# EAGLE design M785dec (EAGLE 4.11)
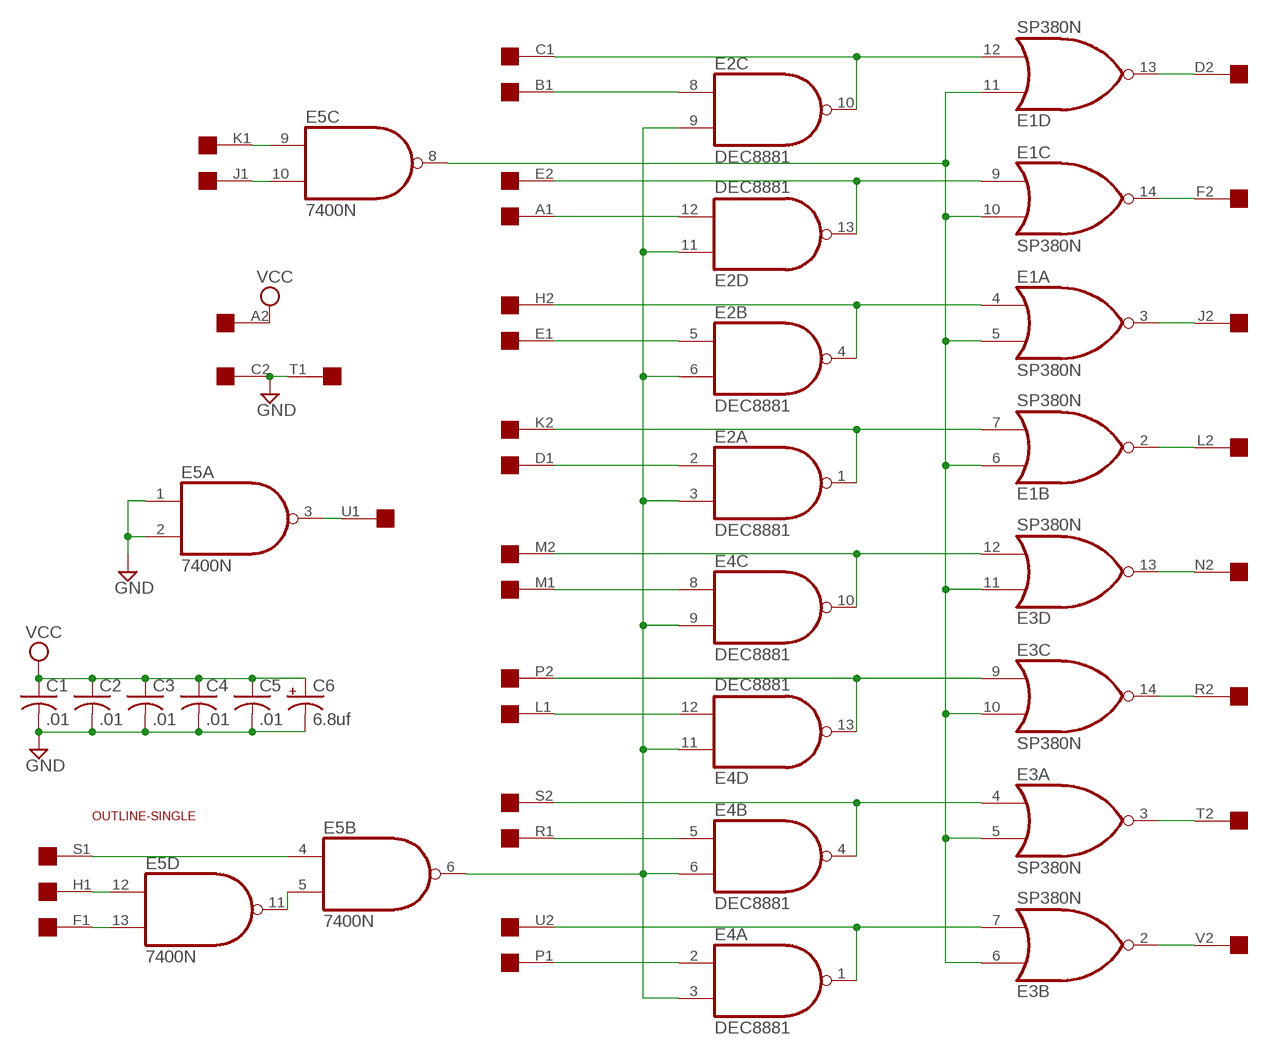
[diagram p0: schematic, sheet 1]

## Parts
C1  .01  C-US050-025X075  [C050-025X075]
C2  .01  C-US050-025X075  [C050-025X075]
C3  .01  C-US050-025X075  [C050-025X075]
C4  .01  C-US050-025X075  [C050-025X075]
C5  .01  C-US050-025X075  [C050-025X075]
C6  6.8uf  CPOL-USE15-5AXIAL  [E15-5]
E1  SP380N  [DIL14]
E2  DEC8881  7401N  [DIL14]
E3  SP380N  [DIL14]
E4  DEC8881  7401N  [DIL14]
E5  7400N  [DIL14]
U$1  SINGLE  [EDGE-CON2]
U$2  OUTLINE-SINGLE  [SINGLE]

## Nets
GND: C1.2 C2.2 C3.2 C4.2 C5.2 C6.- E5.1(A:I0) E5.2(A:I1) U$1.C2 U$1.T1
N$1: E1.5(A:I1) E1.6(B:I0) E1.10(C:I1) E1.11(D:I0) E3.5(A:I1) E3.6(B:I0) E3.10(C:I1) E3.11(D:I0) E5.8(C:O)
N$2: E2.3(A:I1) E2.6(B:I1) E2.9(C:I1) E2.11(D:I0) E4.3(A:I1) E4.6(B:I1) E4.9(C:I1) E4.11(D:I0) E5.6(B:O)
N$3: E3.12(D:I1) E4.10(C:O) U$1.M2
N$4: E3.7(B:I1) E4.1(A:O) U$1.U2
N$5: E4.2(A:I0) U$1.P1
N$6: E4.5(B:I0) U$1.R1
N$7: E3.4(A:I0) E4.4(B:O) U$1.S2
N$8: E4.12(D:I1) U$1.L1
N$9: E3.9(C:I0) E4.13(D:O) U$1.P2
N$10: E4.8(C:I0) U$1.M1
N$11: E1.12(D:I1) E2.10(C:O) U$1.C1
N$12: E2.8(C:I0) U$1.B1
N$13: E1.9(C:I0) E2.13(D:O) U$1.E2
N$14: E2.12(D:I1) U$1.A1
N$15: E1.4(A:I0) E2.4(B:O) U$1.H2
N$16: E2.5(B:I0) U$1.E1
N$17: E1.7(B:I1) E2.1(A:O) U$1.K2
N$18: E2.2(A:I0) U$1.D1
N$19: E5.9(C:I0) U$1.K1
N$20: E5.10(C:I1) U$1.J1
N$21: E1.13(D:O) U$1.D2
N$22: E1.14(C:O) U$1.F2
N$23: E1.3(A:O) U$1.J2
N$24: E1.2(B:O) U$1.L2
N$25: E3.13(D:O) U$1.N2
N$26: E3.14(C:O) U$1.R2
N$27: E3.3(A:O) U$1.T2
N$28: E3.2(B:O) U$1.V2
N$29: E5.4(B:I0) U$1.S1
N$30: E5.5(B:I1) E5.11(D:O)
N$31: E5.12(D:I0) U$1.H1
N$32: E5.13(D:I1) U$1.F1
N$33: E5.3(A:O) U$1.U1
VCC: C1.1 C2.1 C3.1 C4.1 C5.1 C6.+ U$1.A2
Unconnected: U$1.B2 U$1.N1 U$1.V1

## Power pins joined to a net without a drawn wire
GND: E1.1(P:GND) E2.7(P:GND) E3.1(P:GND) E4.7(P:GND) E5.7(P:GND)
VCC: E1.8(P:VCC) E2.14(P:VCC) E3.8(P:VCC) E4.14(P:VCC) E5.14(P:VCC)

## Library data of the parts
C1-C5 = rcl:C-US: CAPACITOR, American symbol
C6 = rcl:CPOL-US: POLARIZED CAPACITOR, American symbol
E1 E3 = dec-con:SP380: Quad NOR gate (use 8640)
E2 E4 = 74xx-jameco:74*01: Quad 2-input NAND gate, open collector
E5 = 74xx-jameco:74*00: Quad 2-input NAND gate
U$1 = dec-con:SINGLE: Single-Height DEC board
U$2 = dec-con:OUTLINE-*: Board outlines for DEC boards.

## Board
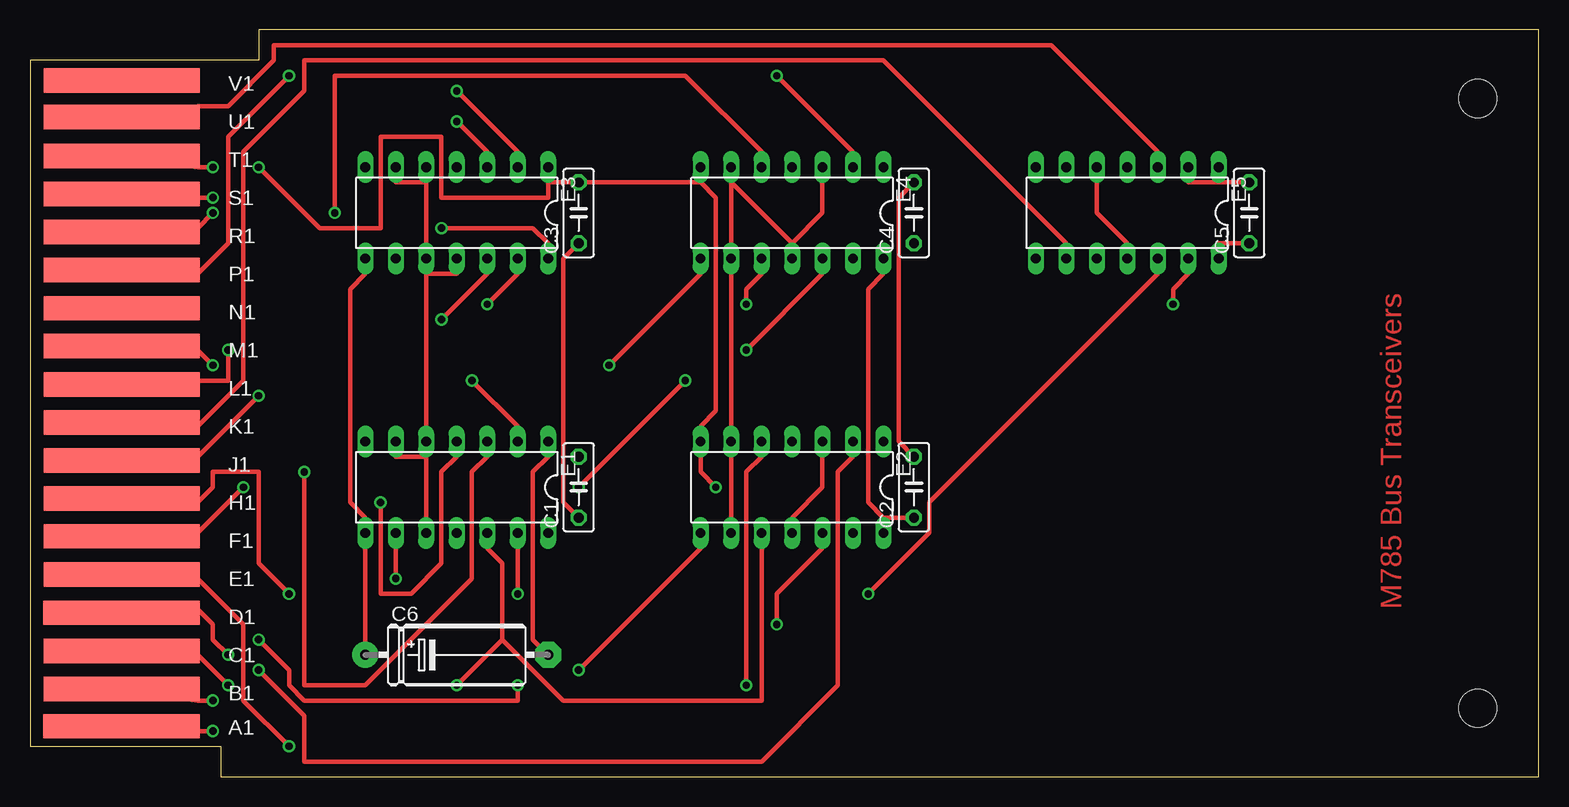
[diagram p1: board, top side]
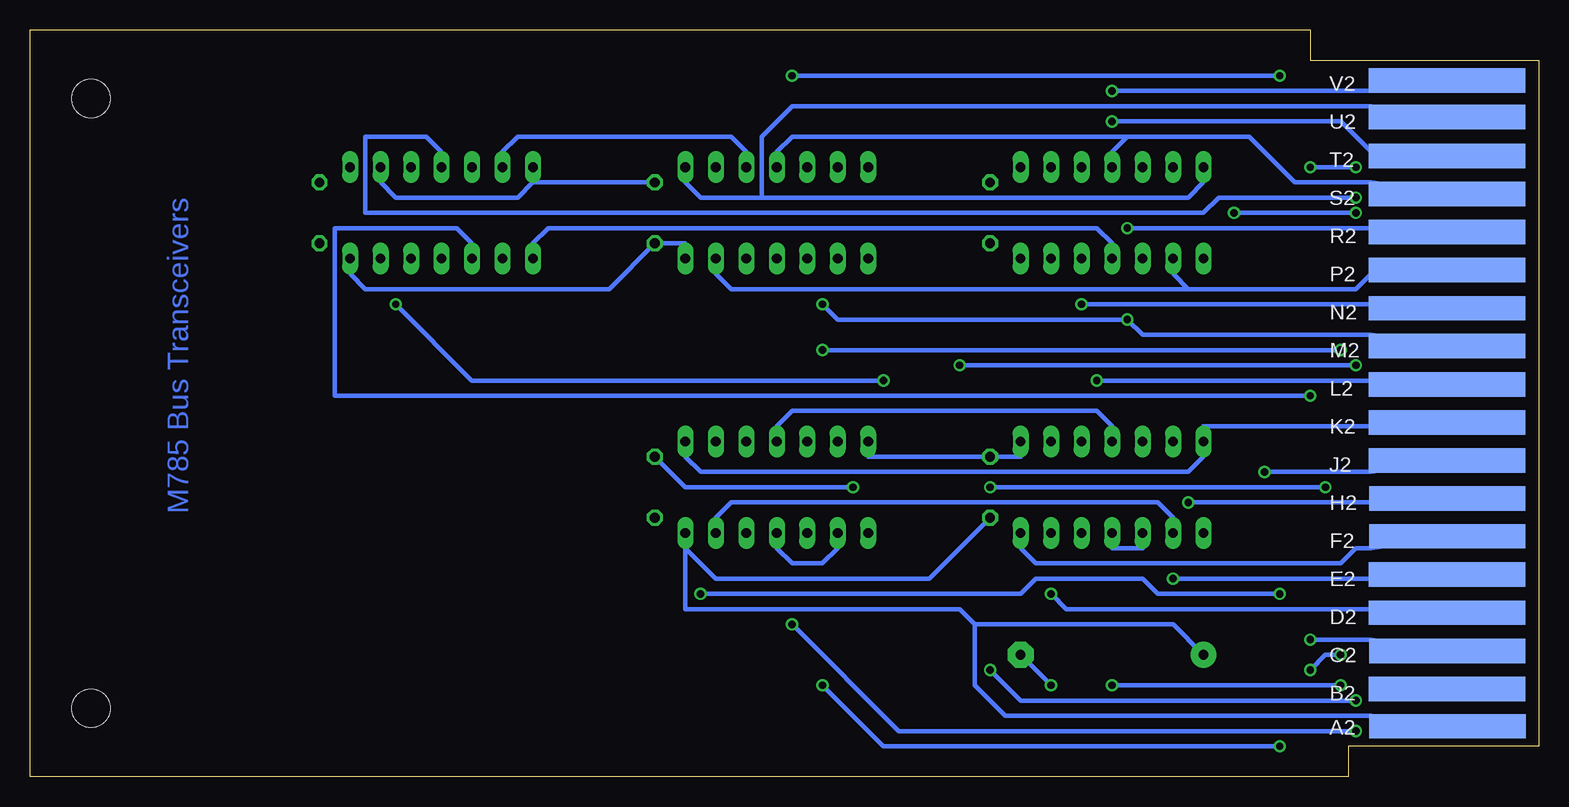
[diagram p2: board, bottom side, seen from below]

Size 125.73 x 62.23 mm. Coordinates in mm from the lower left corner, seen from the top.
Copper layers (1*16): Top 0.035mm / dielectric 1.5mm / Bottom 0.035mm
Design rules "15mils": minimum track width 15mil, minimum drill 24mil, track to track 15mil, track to pad 10mil, pad to pad 10mil, via to via 10mil, smd to smd 10mil, copper to edge 25mil, drill to drill 10mil, minimum pad ring 10mil, minimum via ring 8mil, stop-mask expansion 0mil, vias tented up to drill 0mil, thermal gap 10mil

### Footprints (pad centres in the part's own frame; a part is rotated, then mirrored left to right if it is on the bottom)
C050-025X075 = drill 0.813 octagon: 1 -2.54,0; 2 2.54,0
E15-5 = drill 0.813 pad 2.159 round: + -7.62,0 | drill 0.813 pad 2.159 octagon: - 7.62,0
DIL14 = drill 0.813 long: 1 -7.62,-3.81; 2 -5.08,-3.81; 3 -2.54,-3.81; 4 0,-3.81; 5 2.54,-3.81; 6 5.08,-3.81; 7 7.62,-3.81; 8 7.62,3.81; 9 5.08,3.81; 10 2.54,3.81; 11 0,3.81; 12 -2.54,3.81; 13 -5.08,3.81; 14 -7.62,3.81
EDGE-CON2 = smd 13.017 x 2.032: A1 7.633,4.207; B1 7.639,7.327; C1 7.636,10.489; D1 7.633,13.665; E1 7.642,16.84; F1 7.642,20.041; H1 7.642,23.19; J1 7.642,26.34; K1 7.642,29.515; L1 7.642,32.69; M1 7.642,35.89; N1 7.642,39.04; P1 7.642,42.24; R1 7.642,45.39; S1 7.642,48.565; T1 7.642,51.74; U1 7.642,54.966; V1 7.642,58.026 | smd 13.017 x 2.032 bottom: A2 7.614,4.207; B2 7.642,7.328; C2 7.617,10.49; D2 7.642,13.665; E2 7.642,16.84; F2 7.617,20.041; H2 7.617,23.19; J2 7.642,26.34; K2 7.642,29.515; L2 7.642,32.69; M2 7.642,35.89; N2 7.642,39.04; P2 7.642,42.24; R2 7.642,45.39; S2 7.642,48.565; T2 7.642,51.74; U2 7.642,54.966; V2 7.642,58.026
SINGLE = hole 3.175: 120.65,56.515; 120.65,5.715

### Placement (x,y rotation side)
C1  45.72,24.13 90 top
C2  73.66,24.13 90 top
C3  45.72,46.99 90 top
C4  73.66,46.99 90 top
C5  101.6,46.99 90 top
C6  35.56,10.16 0 top
E1  35.56,24.13 180 top
E2  63.5,24.13 180 top
E3  35.56,46.99 180 top
E4  63.5,46.99 180 top
E5  91.44,46.99 180 top
U$1  0,0 0 top
U$2  0,0 0 top

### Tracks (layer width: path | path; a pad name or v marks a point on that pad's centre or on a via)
GND  (via drill 0.61)
  Top 0.381: 99.06,49.53 96.52,49.53 E5.2 | 99.06,49.53 E5.1 99.06,49.53 | 99.06,49.53 C5.2 | C2.2 72.39,27.94 72.39,48.26 C4.2 | 43.18,49.53 C3.2 55.88,49.53 | 43.18,49.53 E3.1 43.18,49.53 | 55.88,49.53 E4.7 55.88,49.53 | C6.- 41.91,11.43 41.91,25.4 43.18,26.67 E1.1 | 55.88,49.53 57.15,48.26 57.15,30.48 55.88,29.21 E2.7 55.88,26.67 55.88,25.4 v57.15,24.13 | v19.05,11.43 21.59,8.89 21.59,7.62 22.86,6.35 40.64,6.35 v40.64,7.62 | v15.24,50.8 13.97,50.8 U$1.T1 | v19.05,50.8 24.13,45.72 29.21,45.72 29.21,53.34 34.29,53.34 34.29,48.26 43.18,48.26 43.18,49.53
  Bottom 0.381: C4.2 83.82,49.53 | 83.82,49.53 E5.7 83.82,49.53 | 83.82,49.53 85.09,48.26 95.25,48.26 96.52,49.53 E5.2 | E1.1 43.18,26.67 C1.2 55.88,26.67 E2.7 | v19.05,11.43 13.97,11.43 U$1.C2 | v40.64,7.62 C6.- | v19.05,50.8 v15.24,50.8 | C2.2 71.12,24.13 v57.15,24.13
N$1
  Top 0.381: 33.02,26.67 30.48,26.67 E1.6 | 33.02,26.67 E1.5 | 33.02,26.67 33.02,21.59 E1.10 | 33.02,26.67 E1.5 | 33.02,49.53 30.48,49.53 E3.6 | 33.02,49.53 E3.5 33.02,49.53 | 33.02,41.91 35.56,41.91 E3.11 | 33.02,41.91 E3.10 | 33.02,49.53 33.02,44.45 E3.10 | 33.02,41.91 33.02,29.21 E1.5 | 33.02,41.91 E3.10
  Bottom 0.381: E1.10 33.02,19.05 35.56,19.05 E1.11 | E5.8 83.82,44.45 82.55,45.72 36.83,45.72 35.56,44.45 E3.11
N$2
  Top 0.381: 63.5,44.45 66.04,46.99 66.04,49.53 E4.3 | 63.5,44.45 E4.11 63.5,44.45 | E2.11 63.5,21.59 66.04,24.13 66.04,26.67 E2.3 | E2.9 58.42,21.59 58.42,26.67 E2.6 58.42,29.21 58.42,41.91 E4.9 58.42,44.45 58.42,49.53 | 58.42,49.53 E4.6 58.42,49.53 | 58.42,49.53 63.5,44.45
  Bottom 0.381: E5.6 86.36,52.07 85.09,53.34 67.31,53.34 66.04,52.07 E4.3 | E2.11 63.5,19.05 62.23,17.78 59.69,17.78 58.42,19.05 E2.9
N$3  (via drill 0.61)
  Top 0.381: v34.29,38.1 38.1,41.91 E3.12 | v59.69,39.37 59.69,40.64 60.96,41.91 E4.10
  Bottom 0.381: U$1.M2 13.97,36.83 33.02,36.83 v34.29,38.1 58.42,38.1 v59.69,39.37
N$4
  Bottom 0.381: 64.77,48.26 69.85,48.26 71.12,49.53 E4.1 | 64.77,48.26 29.21,48.26 27.94,49.53 E3.7 | 64.77,48.26 64.77,53.34 62.23,55.88 13.97,55.88 U$1.U2
N$5  (via drill 0.61)
  Top 0.381: v62.23,58.42 68.58,52.07 E4.2 | v21.59,58.42 16.51,53.34 16.51,44.45 13.97,41.91 U$1.P1
  Bottom 0.381: v21.59,58.42 v62.23,58.42
N$6  (via drill 0.61)
  Top 0.381: v25.4,46.99 25.4,58.42 54.61,58.42 60.96,52.07 E4.5 | v15.24,46.99 13.97,45.72 U$1.R1
  Bottom 0.381: v15.24,46.99 v25.4,46.99
N$7
  Bottom 0.381: 34.29,53.34 35.56,52.07 E3.4 | 34.29,53.34 24.13,53.34 20.32,49.53 13.97,49.53 U$1.S2 | 34.29,53.34 62.23,53.34 63.5,52.07 E4.4
N$8  (via drill 0.61)
  Top 0.381: v59.69,35.56 66.04,41.91 E4.12 | v16.51,35.56 16.51,33.02 13.97,33.02 U$1.L1
  Bottom 0.381: v16.51,35.56 v59.69,35.56
N$9
  Bottom 0.381: 29.21,40.64 30.48,41.91 E3.9 | 29.21,40.64 15.24,40.64 13.97,41.91 U$1.P2 | 29.21,40.64 67.31,40.64 68.58,41.91 E4.13
N$10  (via drill 0.61)
  Top 0.381: v48.26,34.29 55.88,41.91 E4.8 | v15.24,34.29 13.97,35.56 U$1.M1
  Bottom 0.381: v15.24,34.29 v48.26,34.29
N$11  (via drill 0.61)
  Top 0.381: 39.37,11.43 39.37,17.78 38.1,19.05 E1.12 | 39.37,11.43 44.45,6.35 60.96,6.35 60.96,19.05 E2.10 | v16.51,7.62 13.97,10.16 U$1.C1 | v35.56,7.62 39.37,11.43
  Bottom 0.381: v16.51,7.62 v35.56,7.62
N$12  (via drill 0.61)
  Top 0.381: v45.72,8.89 55.88,19.05 E2.8 | v15.24,6.35 13.97,6.35 U$1.B1
  Bottom 0.381: v45.72,8.89 43.18,6.35 v15.24,6.35
N$13  (via drill 0.61)
  Top 0.381: v30.48,16.51 30.48,19.05 E1.9
  Bottom 0.381: E1.9 30.48,21.59 31.75,22.86 67.31,22.86 68.58,21.59 E2.13 | v30.48,16.51 13.97,16.51 U$1.E2
N$14  (via drill 0.61)
  Top 0.381: v62.23,12.7 62.23,15.24 66.04,19.05 E2.12 | v15.24,3.81 13.97,3.81 U$1.A1
  Bottom 0.381: v62.23,12.7 53.34,3.81 v15.24,3.81
N$15  (via drill 0.61)
  Top 0.381: v29.21,22.86 29.21,15.24 31.75,15.24 34.29,17.78 34.29,25.4 35.56,26.67 E1.4
  Bottom 0.381: E1.4 35.56,29.21 36.83,30.48 62.23,30.48 63.5,29.21 E2.4 | v29.21,22.86 13.97,22.86 U$1.H2
N$16  (via drill 0.61)
  Top 0.381: v59.69,7.62 59.69,25.4 60.96,26.67 E2.5 | v21.59,2.54 17.78,6.35 17.78,12.7 13.97,16.51 U$1.E1
  Bottom 0.381: v59.69,7.62 54.61,2.54 v21.59,2.54
N$17
  Bottom 0.381: U$1.K2 13.97,29.21 27.94,29.21 E1.7 27.94,26.67 29.21,25.4 69.85,25.4 71.12,26.67 E2.1
N$18  (via drill 0.61)
  Top 0.381: v19.05,8.89 22.86,5.08 22.86,1.27 60.96,1.27 67.31,7.62 67.31,25.4 68.58,26.67 E2.2 | v16.51,10.16 15.24,11.43 15.24,12.7 13.97,13.97 U$1.D1
  Bottom 0.381: v19.05,8.89 17.78,10.16 v16.51,10.16
N$19
  Top 0.381: E5.9 86.36,44.45 71.12,59.69 22.86,59.69 22.86,57.15 17.78,52.07 17.78,33.02 13.97,29.21 U$1.K1
N$20  (via drill 0.61)
  Top 0.381: v19.05,31.75 13.97,26.67 U$1.J1
  Bottom 0.381: v19.05,31.75 100.33,31.75 100.33,45.72 90.17,45.72 88.9,44.45 E5.10
N$21  (via drill 0.61)
  Top 0.381: v40.64,15.24 40.64,19.05 E1.13
  Bottom 0.381: v40.64,15.24 39.37,13.97 13.97,13.97 U$1.D2
N$22
  Bottom 0.381: E1.14 43.18,19.05 41.91,17.78 16.51,17.78 15.24,19.05 13.97,19.05 U$1.F2
N$23  (via drill 0.61)
  Top 0.381: v22.86,25.4 22.86,7.62 27.94,7.62 36.83,16.51 36.83,25.4 38.1,26.67 E1.3
  Bottom 0.381: v22.86,25.4 13.97,25.4 U$1.J2
N$24  (via drill 0.61)
  Top 0.381: v36.83,33.02 40.64,29.21 E1.2
  Bottom 0.381: v36.83,33.02 13.97,33.02 U$1.L2
N$25  (via drill 0.61)
  Top 0.381: v38.1,39.37 40.64,41.91 E3.13
  Bottom 0.381: v38.1,39.37 13.97,39.37 U$1.N2
N$26  (via drill 0.61)
  Top 0.381: v34.29,45.72 41.91,45.72 43.18,44.45 E3.14
  Bottom 0.381: v34.29,45.72 13.97,45.72 U$1.R2
N$27  (via drill 0.61)
  Top 0.381: v35.56,54.61 38.1,52.07 E3.3
  Bottom 0.381: v35.56,54.61 16.51,54.61 13.97,52.07 U$1.T2
N$28  (via drill 0.61)
  Top 0.381: v35.56,57.15 40.64,52.07 E3.2
  Bottom 0.381: v35.56,57.15 13.97,57.15 U$1.V2
N$29  (via drill 0.61)
  Top 0.381: v15.24,48.26 13.97,48.26 U$1.S1
  Bottom 0.381: v15.24,48.26 26.67,48.26 27.94,46.99 97.79,46.99 97.79,53.34 92.71,53.34 91.44,52.07 E5.4
N$30
  Top 0.381: E5.11 91.44,44.45 88.9,46.99 88.9,49.53 E5.5
N$31  (via drill 0.61)
  Top 0.381: v69.85,15.24 74.93,20.32 74.93,22.86 93.98,41.91 E5.12 | v21.59,15.24 19.05,17.78 19.05,25.4 15.24,25.4 15.24,24.13 13.97,22.86 U$1.H1
  Bottom 0.381: v69.85,15.24 43.18,15.24 41.91,16.51 33.02,16.51 31.75,15.24 v21.59,15.24
N$32  (via drill 0.61)
  Top 0.381: v95.25,39.37 95.25,40.64 96.52,41.91 E5.13 | v45.72,24.13 v54.61,33.02 | v17.78,24.13 13.97,20.32 U$1.F1
  Bottom 0.381: v95.25,39.37 88.9,33.02 v54.61,33.02 | v17.78,24.13 v45.72,24.13
N$33
  Top 0.381: E5.3 93.98,52.07 85.09,60.96 20.32,60.96 20.32,59.69 16.51,55.88 13.97,55.88 U$1.U1
VCC
  Top 0.381: C1.1 44.45,22.86 44.45,43.18 C3.1 | C5.1 99.06,44.45 E5.14 | 71.12,21.59 C2.1 | 71.12,21.59 E2.14 71.12,21.59 | 71.12,21.59 69.85,22.86 69.85,40.64 71.12,41.91 E4.14 | C6.+ 27.94,19.05 E1.8 27.94,21.59 26.67,22.86 26.67,40.64 27.94,41.91 E3.8
  Bottom 0.381: E4.14 71.12,44.45 C4.1 77.47,40.64 97.79,40.64 99.06,41.91 E5.14 | C1.1 50.8,16.51 68.58,16.51 71.12,19.05 | 71.12,19.05 E2.14 71.12,19.05 | 46.99,12.7 46.99,7.62 44.45,5.08 13.97,5.08 U$1.A2 | 46.99,12.7 30.48,12.7 C6.+ | 71.12,19.05 71.12,13.97 48.26,13.97 46.99,12.7

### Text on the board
Top: M785 Bus Transceivers
Bottom: M785 Bus Transceivers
